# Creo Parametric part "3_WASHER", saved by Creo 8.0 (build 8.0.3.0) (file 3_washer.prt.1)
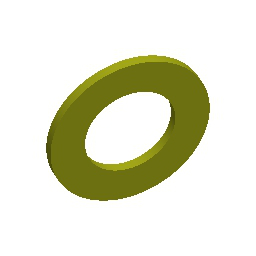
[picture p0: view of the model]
Units: millimeter Newton Second (mmNs); MM, TONNE, SECS

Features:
  1. datum plane "RIGHT"
  2. datum plane "TOP"
  3. datum plane "FRONT"
  4. coordinate system
  5. protrusion
  6. cut

Layers: 0_ALL_AXIS, 0_ALL_CSYS, 0_ALL_CURVES, 0_ALL_PLANES, 0_ALL_POINTS, 0_ALL_SURFS, CUSHION1

Surfaces: 2 plane, 2 cylinder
